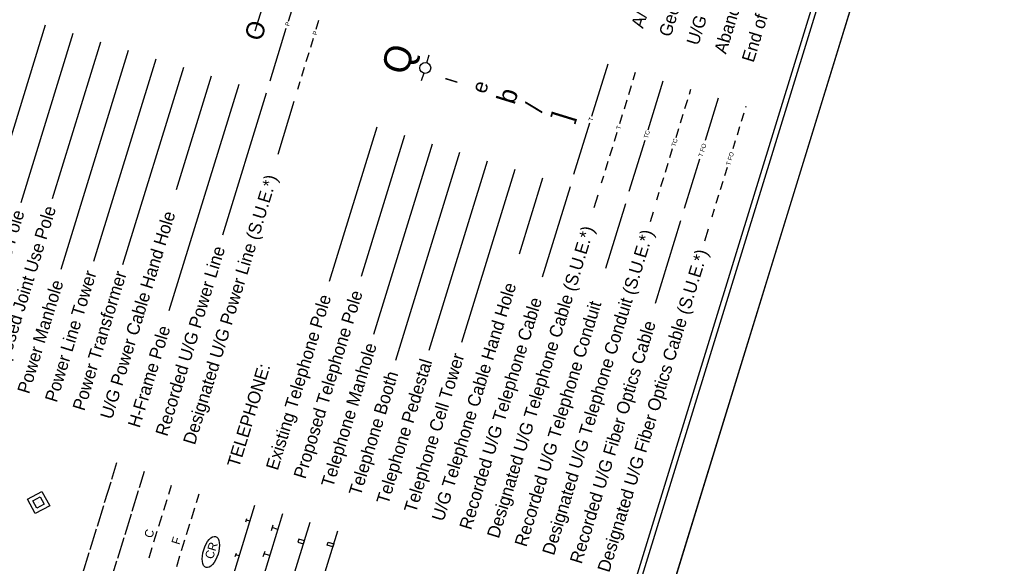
# Model space of a CAD drawing. Extents: x 1347947 to 1350662, y 1027710 to 1030532.
# Drawn here: x 1349990 to 1350662, y 1028788 to 1029165 of the extents above; entities that cross this region are included whole.
import ezdxf

# ---------------------------------------------------------------- set-up
doc = ezdxf.new("R2010")
doc.units = 0
doc.layers.add('Sheet Symbology CELL', color=7, linetype='Continuous')

msp = doc.modelspace()

# ---------------------------------------------------------------- linework, layer by layer
at = {"layer": 'Sheet Symbology CELL'}
for p, q in [((1350165.97, 1027874.54), (1350661.6, 1029483.96)), ((1350176.47, 1029163.45), (1350187.33, 1029198.72)), ((1350153.5, 1029156.82), (1350159.39, 1029175.94)), ((1350008.22, 1029160.74), (1349969.69, 1029035.63)), ((1350195.67, 1029157.86), (1350197.58, 1029164.07)), ((1350027.33, 1029154.86), (1349991.27, 1029037.77)), ((1350163.78, 1029122.27), (1350174.99, 1029158.67)), ((1350046.45, 1029148.97), (1350013.04, 1029040.49)), ((1350191.87, 1029145.53), (1350193.79, 1029151.74)), ((1350065.56, 1029143.08), (1350018.91, 1028991.6)), ((1350188.78, 1029135.49), (1350190.7, 1029141.71)), ((1350084.67, 1029137.2), (1350041.56, 1028997.19)), ((1350272.25, 1029134.68), (1350273.91, 1029140.05)), ((1350386.44, 1029097.78), (1350397.58, 1029133.97)), ((1350103.79, 1029131.31), (1350061.73, 1028994.74)), ((1350185.69, 1029125.46), (1350187.61, 1029131.67)), ((1350270.05, 1029127.51), (1350268.39, 1029122.13)), ((1350415.06, 1029122.76), (1350416.7, 1029128.09)), ((1350122.9, 1029125.43), (1350098.67, 1029046.75)), ((1350182.9, 1029116.38), (1350184.52, 1029121.64)), ((1350425.39, 1029088.36), (1350435.81, 1029122.2)), ((1350142.02, 1029119.54), (1350093.78, 1028962.9)), ((1350411.97, 1029112.72), (1350413.88, 1029118.94)), ((1350453.92, 1029113.05), (1350454.93, 1029116.31)), ((1350161.13, 1029113.65), (1350130.83, 1029015.25)), ((1350180.25, 1029107.77), (1350169, 1029071.25)), ((1350408.88, 1029102.69), (1350410.79, 1029108.9)), ((1350450.83, 1029103.02), (1350452.75, 1029109.23)), ((1350465.03, 1029081.16), (1350474.04, 1029110.43)), ((1350492.96, 1029103.91), (1350493.16, 1029104.54)), ((1350405.79, 1029092.65), (1350407.7, 1029098.87)), ((1350447.74, 1029092.98), (1350449.66, 1029099.19)), ((1350490.02, 1029094.35), (1350491.78, 1029100.09)), ((1350237.59, 1029090.11), (1350204.66, 1028983.18)), ((1350374.04, 1029057.52), (1350384.97, 1029093)), ((1350444.65, 1029082.95), (1350446.56, 1029089.16)), ((1350487.07, 1029084.79), (1350488.84, 1029090.53)), ((1350256.7, 1029084.22), (1350226.66, 1028986.68)), ((1350401.99, 1029080.33), (1350403.9, 1029086.54)), ((1350412.27, 1029045.74), (1350423.18, 1029081.19)), ((1350484.13, 1029075.24), (1350485.9, 1029080.97)), ((1350275.82, 1029078.33), (1350235.24, 1028946.58)), ((1350398.9, 1029070.29), (1350400.81, 1029076.5)), ((1350440.38, 1029069.09), (1350442.3, 1029075.3)), ((1350294.93, 1029072.45), (1350250.64, 1028928.61)), ((1350450.5, 1029033.97), (1350461.05, 1029068.26)), ((1350314.04, 1029066.56), (1350273.68, 1028935.47)), ((1350333.16, 1029060.68), (1350296.3, 1028941)), ((1350395.81, 1029060.26), (1350397.72, 1029066.47)), ((1350437.29, 1029059.05), (1350439.21, 1029065.27)), ((1350478.39, 1029056.6), (1350480.16, 1029062.33)), ((1350352.27, 1029054.79), (1350336.07, 1029002.19)), ((1350393.15, 1029051.63), (1350394.63, 1029056.43)), ((1350434.2, 1029049.02), (1350436.12, 1029055.23)), ((1350371.39, 1029048.9), (1350352.09, 1028986.24)), ((1350475.45, 1029047.04), (1350477.21, 1029052.78)), ((1350390.5, 1029043.02), (1350387.81, 1029034.28)), ((1350431.38, 1029039.86), (1350433.03, 1029045.2)), ((1350472.51, 1029037.49), (1350474.27, 1029043.22)), ((1350409.62, 1029037.13), (1350395.8, 1028992.28)), ((1350469.61, 1029028.08), (1350471.33, 1029033.66)), ((1350428.73, 1029031.24), (1350426.65, 1029024.49)), ((1350447.84, 1029025.36), (1350430.18, 1028967.99)), ((1350466.96, 1029019.47), (1350464.44, 1029011.29)), ((1350054.28, 1028846.46), (1350057.81, 1028857.93)), ((1350073.39, 1028840.58), (1350076.93, 1028852.05)), ((1350049.28, 1028830.22), (1350053.69, 1028844.55)), ((1350068.39, 1028824.33), (1350072.81, 1028838.67)), ((1350095.27, 1028842.05), (1350093.39, 1028835.94)), ((1350092.24, 1028832.21), (1350089.93, 1028824.71)), ((1350114.39, 1028836.17), (1350112.5, 1028830.05)), ((1350003.55, 1028830.33), (1350003.55, 1028830.33)), ((1350044.27, 1028813.97), (1350048.69, 1028828.31)), ((1350111.36, 1028826.32), (1350109.04, 1028818.82)), ((1350129.68, 1028751.93), (1350153.22, 1028828.39)), ((1350063.39, 1028808.08), (1350067.8, 1028822.42)), ((1350088.84, 1028821.17), (1350086.56, 1028813.77)), ((1350147.05, 1028816.83), (1350147.78, 1028819.22)), ((1350172.34, 1028822.5), (1350148.79, 1028746.04)), ((1350039.27, 1028797.72), (1350043.68, 1028812.06)), ((1350107.96, 1028815.29), (1350105.68, 1028807.88)), ((1350149.8, 1028817.29), (1350147.41, 1028818.03)), ((1350164.65, 1028810.98), (1350165.83, 1028814.8)), ((1350169.02, 1028811.73), (1350165.24, 1028812.89)), ((1350167.9, 1028740.16), (1350191.45, 1028816.61)), ((1350058.38, 1028791.84), (1350062.8, 1028806.17)), ((1350085.47, 1028810.23), (1350083.18, 1028802.78)), ((1350187.02, 1028734.27), (1350210.56, 1028810.73)), ((1350082.01, 1028799), (1350079.78, 1028791.74)), ((1350104.59, 1028804.34), (1350102.29, 1028796.89)), ((1350034.27, 1028781.48), (1350038.68, 1028795.81)), ((1350101.13, 1028793.11), (1350098.89, 1028785.85)), ((1350139.69, 1028792.94), (1350140.42, 1028795.33)), ((1350142.45, 1028793.4), (1350140.06, 1028794.13)), ((1350159.06, 1028792.82), (1350160.24, 1028796.64)), ((1350163.43, 1028793.57), (1350159.65, 1028794.73)), ((1350053.38, 1028775.59), (1350057.8, 1028789.93))]:
    msp.add_line(p, q, dxfattribs=at)
for points in [[(1350165.97, 1027874.54), (1350661.6, 1029483.96), (1349610.32, 1029807.71), (1349114.69, 1028198.29)], [(1350148.34, 1027893.58), (1350638.82, 1029486.26), (1349630.46, 1029796.8), (1349139.98, 1028204.11)], [(1349629.21, 1029784.1), (1349187.74, 1028350.54), (1350190.26, 1028041.81), (1350631.74, 1029475.37)], [(1349995.86, 1028832.7), (1350005.92, 1028838.02), (1350011.24, 1028827.96), (1350001.18, 1028822.63)], [(1349999.7, 1028831.51), (1350004.74, 1028834.17), (1350007.4, 1028829.14), (1350002.37, 1028826.48)], [(1350186.88, 1028801.78), (1350187.47, 1028803.69), (1350183.65, 1028804.87), (1350183.06, 1028802.95)], [(1350203.35, 1028800.88), (1350203.93, 1028802.79), (1350207.76, 1028801.61), (1350207.17, 1028799.7)]]:
    msp.add_lwpolyline(points, close=True, dxfattribs=at)
msp.add_circle((1350271.13, 1029131.06), 3.75, dxfattribs=at)
msp.add_ellipse((1350122.76, 1028796.04), major_axis=(3.3, 10.72), ratio=0.462467, dxfattribs=at)

# ---------------------------------------------------------------- texts
for s, height, p in [('Abandoned According to Utility Records', 8.75, (1350479.16, 1029140.27)), ('A/G Tank; Water, Gas, Oil', 8.75, (1350421.81, 1029157.93)), ('Geoenvironmental Boring', 8.75, (1350440.93, 1029152.04)), ('U/G Test Hole (S.U.E.*)', 8.75, (1350460.04, 1029146.16)), ('End of Information', 8.75, (1350498.27, 1029134.38)), ('O', 12.5, (1350157.63, 1029149.01)), ('P', 3, (1350176.9, 1029159.75)), ('P', 3, (1350195.9, 1029153.5)), ('Q', 18.75, (1350258.21, 1029125.23)), ('l', 8.25, (1350292.97, 1029120.02)), ('e', 10.5, (1350312.83, 1029112.73)), ('b', 13.2, (1350332.83, 1029105.15)), ('/', 12.5, (1350351.72, 1029099.7)), (']', 13.5, (1350371.16, 1029093.19)), ('T', 3, (1350386.86, 1029094.04)), ('T', 3, (1350406, 1029088.25)), ('TC', 3, (1350425.01, 1029082.04)), ('TC', 3, (1350444.2, 1029076.39)), ('T FO', 3, (1350462.93, 1029069.25)), ('T FO', 3, (1350482.03, 1029063.33)), ('Designated U/G Power Line (S.U.E.*)', 8.75, (1350111.67, 1028869.71)), ('Proposed Joint Use Pole', 8.75, (1349977.87, 1028910.88)), ('Existing Joint Use Pole', 8.75, (1349958.74, 1028916.76)), ('U/G Power Cable Hand Hole', 8.75, (1350054.33, 1028887.35)), ('Designated U/G Telephone Cable (S.U.E.*)', 8.75, (1350321.94, 1028804.95)), ('Designated U/G Telephone Conduit (S.U.E.*)', 8.75, (1350360.16, 1028793.18)), ('Recorded U/G Power Line', 8.75, (1350092.56, 1028875.58)), ('Designated U/G Fiber Optics Cable (S.U.E.*)', 8.75, (1350398.39, 1028781.41)), ('Power Line Tower', 8.75, (1350016.09, 1028899.11)), ('Power Transformer', 8.75, (1350035.2, 1028893.22)), ('Power Manhole', 8.75, (1349996.99, 1028905)), ('U/G Telephone Cable Hand Hole', 8.75, (1350283.71, 1028816.72)), ('Existing Telephone Pole', 8.75, (1350169.02, 1028852.03)), ('Proposed Telephone Pole', 8.75, (1350188.13, 1028846.14)), ('Recorded U/G Telephone Cable', 8.75, (1350302.82, 1028810.84)), ('Recorded U/G Telephone Conduit', 8.75, (1350341.05, 1028799.07)), ('Recorded U/G Fiber Optics Cable', 8.75, (1350379.28, 1028787.29)), ('H-Frame Pole', 8.75, (1350073.45, 1028881.46)), ('Telephone Manhole', 8.75, (1350207.25, 1028840.26)), ('Telephone Cell Tower', 8.75, (1350264.59, 1028822.61)), ('TELEPHONE:', 8.75, (1350142.22, 1028853.94)), ('Telephone Pedestal', 8.75, (1350245.47, 1028828.49)), ('Telephone Booth', 8.75, (1350226.36, 1028834.37)), ('C', 5.93, (1350082.12, 1028805.25)), ('F', 5.93, (1350100.99, 1028800.69)), ('CR', 6, (1350124.2, 1028790.67))]:
    msp.add_text(s, height=height, rotation=72.88342, dxfattribs=at).set_placement(p)

doc.saveas('drawing.dxf')
